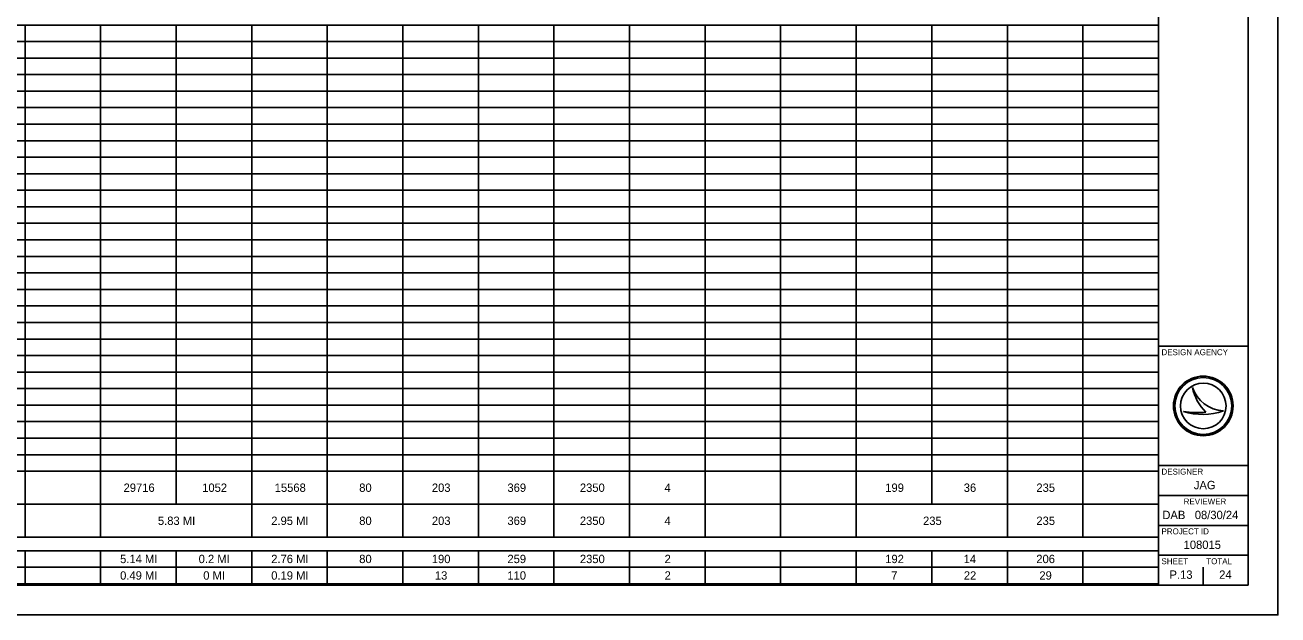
# Model space of a CAD drawing. Extents: x 0 to 34, y 0 to 22.
# Drawn here: x 13.03 to 34, y 0 to 9.88 of the extents above; entities that cross this region are included whole.
import ezdxf

# ---------------------------------------------------------------- set-up
doc = ezdxf.new("R2010")
doc.units = 0
for name, color, linetype in [('SH_Border', 7, 'Continuous'), ('SH_Cut_Line', 7, 'Continuous'), ('SH_Data', 7, 'Continuous'), ('SH_Text', 7, 'Continuous')]:
    doc.layers.add(name, color=color, linetype=linetype)

msp = doc.modelspace()

# ---------------------------------------------------------------- linework, layer by layer
at = {"layer": 'SH_Border'}
for p, q in [((32, 0.5), (32, 21.5)), ((32, 4.5), (33.5, 4.5)), ((32, 2.5), (33.5, 2.5)), ((32, 2), (33.5, 2)), ((32, 1.5), (33.5, 1.5)), ((32, 1), (33.5, 1))]:
    msp.add_line(p, q, dxfattribs=at)
msp.add_lwpolyline([(1.5, 21.5), (33.5, 21.5), (33.5, 0.5), (1.5, 0.5)], close=True, dxfattribs=at)
at = {"layer": 'SH_Cut_Line'}
msp.add_lwpolyline([(0, 0), (34, 0), (34, 22), (0, 22)], close=True, dxfattribs=at)
at = {"layer": 'SH_Data'}
for p, q in [((32.567, 3.81), (32.567, 3.81)), ((32.417, 3.41), (32.417, 3.41)), ((32.75, 3.5), (32.75, 3.5)), ((33.087, 3.419), (33.087, 3.419)), ((32.375, 0.675), (32.375, 0.675)), ((32.75, 0.5), (32.75, 0.8))]:
    msp.add_line(p, q, dxfattribs=at)
for radius in [0.5, 0.477, 0.477, 0.382]:
    msp.add_circle((32.75, 3.5), radius, dxfattribs=at)
for centre, radius, start, end in [((33.116, 3.998), 0.58, 198.9257, 198.9319), ((33.347, 3.97), 0.796, 191.6379, 191.6421), ((33.116, 3.998), 0.58, 198.9319, 267.1657), ((33.347, 3.97), 0.796, 191.6421, 226.0947), ((32.739, 4.37), 1.013, 251.4576, 290.0832), ((32.648, 4.654), 1.266, 259.4964, 259.4995), ((32.739, 4.37), 1.013, 251.4527, 251.4576), ((32.648, 4.654), 1.266, 259.4995, 276.6672)]:
    msp.add_arc(centre, radius, start, end, dxfattribs=at)
at = {"layer": 'SH_Text'}
for p, q in [((8.427, 9.878), (13.026, 9.878)), ((13.026, 9.878), (15.556, 9.878)), ((13.026, 9.878), (13.026, 9.325)), ((14.291, 9.878), (14.291, 9.325)), ((15.556, 9.878), (23.145, 9.878)), ((15.556, 9.878), (15.556, 9.325)), ((16.821, 9.878), (16.821, 9.325)), ((18.086, 9.878), (18.086, 9.325)), ((19.351, 9.878), (19.351, 9.325)), ((20.616, 9.878), (20.616, 9.325)), ((21.88, 9.878), (21.88, 9.325)), ((23.145, 9.878), (24.41, 9.878)), ((23.145, 9.878), (23.145, 9.325)), ((24.41, 9.878), (25.675, 9.878)), ((24.41, 9.878), (24.41, 9.325)), ((25.675, 9.878), (26.94, 9.878)), ((25.675, 9.878), (25.675, 9.325)), ((26.94, 9.878), (28.205, 9.878)), ((26.94, 9.878), (26.94, 9.325)), ((28.205, 9.878), (29.47, 9.878)), ((28.205, 9.878), (28.205, 9.325)), ((29.47, 9.878), (30.735, 9.878)), ((29.47, 9.878), (29.47, 9.325)), ((30.735, 9.878), (32, 9.878)), ((30.735, 9.878), (30.735, 9.325)), ((32, 9.878), (32, 9.325)), ((8.427, 9.602), (13.026, 9.602)), ((13.026, 9.602), (15.556, 9.602)), ((15.556, 9.602), (23.145, 9.602)), ((23.145, 9.602), (24.41, 9.602)), ((24.41, 9.602), (25.675, 9.602)), ((25.675, 9.602), (26.94, 9.602)), ((26.94, 9.602), (28.205, 9.602)), ((28.205, 9.602), (29.47, 9.602)), ((29.47, 9.602), (30.735, 9.602)), ((30.735, 9.602), (32, 9.602)), ((8.427, 9.325), (13.026, 9.325)), ((13.026, 9.325), (15.556, 9.325)), ((13.026, 9.325), (13.026, 8.495)), ((14.291, 9.325), (14.291, 8.495)), ((15.556, 9.325), (23.145, 9.325)), ((15.556, 9.325), (15.556, 8.495)), ((16.821, 9.325), (16.821, 8.495)), ((18.086, 9.325), (18.086, 8.495)), ((19.351, 9.325), (19.351, 8.495)), ((20.616, 9.325), (20.616, 8.495)), ((21.88, 9.325), (21.88, 8.495)), ((23.145, 9.325), (24.41, 9.325)), ((23.145, 9.325), (23.145, 8.495)), ((24.41, 9.325), (25.675, 9.325)), ((24.41, 9.325), (24.41, 8.495)), ((25.675, 9.325), (26.94, 9.325)), ((25.675, 9.325), (25.675, 8.495)), ((26.94, 9.325), (28.205, 9.325)), ((26.94, 9.325), (26.94, 8.495)), ((28.205, 9.325), (29.47, 9.325)), ((28.205, 9.325), (28.205, 8.495)), ((29.47, 9.325), (30.735, 9.325)), ((29.47, 9.325), (29.47, 8.495)), ((30.735, 9.325), (32, 9.325)), ((30.735, 9.325), (30.735, 8.495)), ((32, 9.325), (32, 8.495)), ((8.427, 9.048), (13.026, 9.048)), ((13.026, 9.048), (15.556, 9.048)), ((15.556, 9.048), (23.145, 9.048)), ((23.145, 9.048), (24.41, 9.048)), ((24.41, 9.048), (25.675, 9.048)), ((25.675, 9.048), (26.94, 9.048)), ((26.94, 9.048), (28.205, 9.048)), ((28.205, 9.048), (29.47, 9.048)), ((29.47, 9.048), (30.735, 9.048)), ((30.735, 9.048), (32, 9.048)), ((8.427, 8.772), (13.026, 8.772)), ((13.026, 8.772), (15.556, 8.772)), ((15.556, 8.772), (23.145, 8.772)), ((23.145, 8.772), (24.41, 8.772)), ((24.41, 8.772), (25.675, 8.772)), ((25.675, 8.772), (26.94, 8.772)), ((26.94, 8.772), (28.205, 8.772)), ((28.205, 8.772), (29.47, 8.772)), ((29.47, 8.772), (30.735, 8.772)), ((30.735, 8.772), (32, 8.772)), ((8.427, 8.495), (13.026, 8.495)), ((13.026, 8.495), (15.556, 8.495)), ((13.026, 8.495), (13.026, 7.941)), ((14.291, 8.495), (14.291, 7.941)), ((15.556, 8.495), (23.145, 8.495)), ((15.556, 8.495), (15.556, 7.941)), ((16.821, 8.495), (16.821, 7.941)), ((18.086, 8.495), (18.086, 7.941)), ((19.351, 8.495), (19.351, 7.941)), ((20.616, 8.495), (20.616, 7.941)), ((21.88, 8.495), (21.88, 7.941)), ((23.145, 8.495), (24.41, 8.495)), ((23.145, 8.495), (23.145, 7.941)), ((24.41, 8.495), (25.675, 8.495)), ((24.41, 8.495), (24.41, 7.941)), ((25.675, 8.495), (26.94, 8.495)), ((25.675, 8.495), (25.675, 7.941)), ((26.94, 8.495), (28.205, 8.495)), ((26.94, 8.495), (26.94, 7.941)), ((28.205, 8.495), (29.47, 8.495)), ((28.205, 8.495), (28.205, 7.941)), ((29.47, 8.495), (30.735, 8.495)), ((29.47, 8.495), (29.47, 7.941)), ((30.735, 8.495), (32, 8.495)), ((30.735, 8.495), (30.735, 7.941)), ((32, 8.495), (32, 7.941)), ((8.427, 8.218), (13.026, 8.218)), ((13.026, 8.218), (15.556, 8.218)), ((15.556, 8.218), (23.145, 8.218)), ((23.145, 8.218), (24.41, 8.218)), ((24.41, 8.218), (25.675, 8.218)), ((25.675, 8.218), (26.94, 8.218)), ((26.94, 8.218), (28.205, 8.218)), ((28.205, 8.218), (29.47, 8.218)), ((29.47, 8.218), (30.735, 8.218)), ((30.735, 8.218), (32, 8.218)), ((8.427, 7.941), (13.026, 7.941)), ((13.026, 7.941), (15.556, 7.941)), ((13.026, 7.941), (13.026, 7.111)), ((14.291, 7.941), (14.291, 7.111)), ((15.556, 7.941), (23.145, 7.941)), ((15.556, 7.941), (15.556, 7.111)), ((16.821, 7.941), (16.821, 7.111)), ((18.086, 7.941), (18.086, 7.111)), ((19.351, 7.941), (19.351, 7.111)), ((20.616, 7.941), (20.616, 7.111)), ((21.88, 7.941), (21.88, 7.111)), ((23.145, 7.941), (24.41, 7.941)), ((23.145, 7.941), (23.145, 7.111)), ((24.41, 7.941), (25.675, 7.941)), ((24.41, 7.941), (24.41, 7.111)), ((25.675, 7.941), (26.94, 7.941)), ((25.675, 7.941), (25.675, 7.111)), ((26.94, 7.941), (28.205, 7.941)), ((26.94, 7.941), (26.94, 7.111)), ((28.205, 7.941), (29.47, 7.941)), ((28.205, 7.941), (28.205, 7.111)), ((29.47, 7.941), (30.735, 7.941)), ((29.47, 7.941), (29.47, 7.111)), ((30.735, 7.941), (32, 7.941)), ((30.735, 7.941), (30.735, 7.111)), ((32, 7.941), (32, 7.111)), ((8.427, 7.665), (13.026, 7.665)), ((13.026, 7.665), (15.556, 7.665)), ((15.556, 7.665), (23.145, 7.665)), ((23.145, 7.665), (24.41, 7.665)), ((24.41, 7.665), (25.675, 7.665)), ((25.675, 7.665), (26.94, 7.665)), ((26.94, 7.665), (28.205, 7.665)), ((28.205, 7.665), (29.47, 7.665)), ((29.47, 7.665), (30.735, 7.665)), ((30.735, 7.665), (32, 7.665)), ((8.427, 7.388), (13.026, 7.388)), ((13.026, 7.388), (15.556, 7.388)), ((15.556, 7.388), (23.145, 7.388)), ((23.145, 7.388), (24.41, 7.388)), ((24.41, 7.388), (25.675, 7.388)), ((25.675, 7.388), (26.94, 7.388)), ((26.94, 7.388), (28.205, 7.388)), ((28.205, 7.388), (29.47, 7.388)), ((29.47, 7.388), (30.735, 7.388)), ((30.735, 7.388), (32, 7.388)), ((8.427, 7.111), (13.026, 7.111)), ((13.026, 7.111), (15.556, 7.111)), ((13.026, 7.111), (13.026, 6.558)), ((14.291, 7.111), (14.291, 6.558)), ((15.556, 7.111), (23.145, 7.111)), ((15.556, 7.111), (15.556, 6.558)), ((16.821, 7.111), (16.821, 6.558)), ((18.086, 7.111), (18.086, 6.558)), ((19.351, 7.111), (19.351, 6.558)), ((20.616, 7.111), (20.616, 6.558)), ((21.88, 7.111), (21.88, 6.558)), ((23.145, 7.111), (24.41, 7.111)), ((23.145, 7.111), (23.145, 6.558)), ((24.41, 7.111), (25.675, 7.111)), ((24.41, 7.111), (24.41, 6.558)), ((25.675, 7.111), (26.94, 7.111)), ((25.675, 7.111), (25.675, 6.558)), ((26.94, 7.111), (28.205, 7.111)), ((26.94, 7.111), (26.94, 6.558)), ((28.205, 7.111), (29.47, 7.111)), ((28.205, 7.111), (28.205, 6.558)), ((29.47, 7.111), (30.735, 7.111)), ((29.47, 7.111), (29.47, 6.558)), ((30.735, 7.111), (32, 7.111)), ((30.735, 7.111), (30.735, 6.558)), ((32, 7.111), (32, 6.558)), ((8.427, 6.835), (13.026, 6.835)), ((13.026, 6.835), (15.556, 6.835)), ((15.556, 6.835), (23.145, 6.835)), ((23.145, 6.835), (24.41, 6.835)), ((24.41, 6.835), (25.675, 6.835)), ((25.675, 6.835), (26.94, 6.835)), ((26.94, 6.835), (28.205, 6.835)), ((28.205, 6.835), (29.47, 6.835)), ((29.47, 6.835), (30.735, 6.835)), ((30.735, 6.835), (32, 6.835)), ((8.427, 6.558), (13.026, 6.558)), ((13.026, 6.558), (15.556, 6.558)), ((13.026, 6.558), (13.026, 1.3)), ((14.291, 6.558), (14.291, 1.3)), ((15.556, 6.558), (23.145, 6.558)), ((15.556, 6.558), (15.556, 1.854)), ((16.821, 6.558), (16.821, 1.3)), ((18.086, 6.558), (18.086, 1.3)), ((19.351, 6.558), (19.351, 1.3)), ((20.616, 6.558), (20.616, 1.3)), ((21.88, 6.558), (21.88, 1.3)), ((23.145, 6.558), (24.41, 6.558)), ((23.145, 6.558), (23.145, 1.3)), ((24.41, 6.558), (25.675, 6.558)), ((24.41, 6.558), (24.41, 1.3)), ((25.675, 6.558), (26.94, 6.558)), ((25.675, 6.558), (25.675, 1.3)), ((26.94, 6.558), (28.205, 6.558)), ((26.94, 6.558), (26.94, 1.3)), ((28.205, 6.558), (29.47, 6.558)), ((28.205, 6.558), (28.205, 1.854)), ((29.47, 6.558), (30.735, 6.558)), ((29.47, 6.558), (29.47, 1.3)), ((30.735, 6.558), (32, 6.558)), ((30.735, 6.558), (30.735, 1.3)), ((32, 6.558), (32, 0.523)), ((8.427, 6.281), (13.026, 6.281)), ((13.026, 6.281), (15.556, 6.281)), ((15.556, 6.281), (23.145, 6.281)), ((23.145, 6.281), (24.41, 6.281)), ((24.41, 6.281), (25.675, 6.281)), ((25.675, 6.281), (26.94, 6.281)), ((26.94, 6.281), (28.205, 6.281)), ((28.205, 6.281), (29.47, 6.281)), ((29.47, 6.281), (30.735, 6.281)), ((30.735, 6.281), (32, 6.281)), ((8.427, 6.004), (13.026, 6.004)), ((13.026, 6.004), (15.556, 6.004)), ((15.556, 6.004), (23.145, 6.004)), ((23.145, 6.004), (24.41, 6.004)), ((24.41, 6.004), (25.675, 6.004)), ((25.675, 6.004), (26.94, 6.004)), ((26.94, 6.004), (28.205, 6.004)), ((28.205, 6.004), (29.47, 6.004)), ((29.47, 6.004), (30.735, 6.004)), ((30.735, 6.004), (32, 6.004)), ((8.427, 5.728), (13.026, 5.728)), ((13.026, 5.728), (15.556, 5.728)), ((15.556, 5.728), (23.145, 5.728)), ((23.145, 5.728), (24.41, 5.728)), ((24.41, 5.728), (25.675, 5.728)), ((25.675, 5.728), (26.94, 5.728)), ((26.94, 5.728), (28.205, 5.728)), ((28.205, 5.728), (29.47, 5.728)), ((29.47, 5.728), (30.735, 5.728)), ((30.735, 5.728), (32, 5.728)), ((8.427, 5.451), (13.026, 5.451)), ((13.026, 5.451), (15.556, 5.451)), ((15.556, 5.451), (23.145, 5.451)), ((23.145, 5.451), (24.41, 5.451)), ((24.41, 5.451), (25.675, 5.451)), ((25.675, 5.451), (26.94, 5.451)), ((26.94, 5.451), (28.205, 5.451)), ((28.205, 5.451), (29.47, 5.451)), ((29.47, 5.451), (30.735, 5.451)), ((30.735, 5.451), (32, 5.451)), ((8.427, 5.174), (13.026, 5.174)), ((13.026, 5.174), (15.556, 5.174)), ((15.556, 5.174), (23.145, 5.174)), ((23.145, 5.174), (24.41, 5.174)), ((24.41, 5.174), (25.675, 5.174)), ((25.675, 5.174), (26.94, 5.174)), ((26.94, 5.174), (28.205, 5.174)), ((28.205, 5.174), (29.47, 5.174)), ((29.47, 5.174), (30.735, 5.174)), ((30.735, 5.174), (32, 5.174)), ((8.427, 4.898), (13.026, 4.898)), ((13.026, 4.898), (15.556, 4.898)), ((15.556, 4.898), (23.145, 4.898)), ((23.145, 4.898), (24.41, 4.898)), ((24.41, 4.898), (25.675, 4.898)), ((25.675, 4.898), (26.94, 4.898)), ((26.94, 4.898), (28.205, 4.898)), ((28.205, 4.898), (29.47, 4.898)), ((29.47, 4.898), (30.735, 4.898)), ((30.735, 4.898), (32, 4.898)), ((8.427, 4.621), (13.026, 4.621)), ((13.026, 4.621), (15.556, 4.621)), ((15.556, 4.621), (23.145, 4.621)), ((23.145, 4.621), (24.41, 4.621)), ((24.41, 4.621), (25.675, 4.621)), ((25.675, 4.621), (26.94, 4.621)), ((26.94, 4.621), (28.205, 4.621)), ((28.205, 4.621), (29.47, 4.621)), ((29.47, 4.621), (30.735, 4.621)), ((30.735, 4.621), (32, 4.621)), ((8.427, 4.344), (13.026, 4.344)), ((13.026, 4.344), (15.556, 4.344)), ((15.556, 4.344), (23.145, 4.344)), ((23.145, 4.344), (24.41, 4.344)), ((24.41, 4.344), (25.675, 4.344)), ((25.675, 4.344), (26.94, 4.344)), ((26.94, 4.344), (28.205, 4.344)), ((28.205, 4.344), (29.47, 4.344)), ((29.47, 4.344), (30.735, 4.344)), ((30.735, 4.344), (32, 4.344)), ((8.427, 4.068), (13.026, 4.068)), ((13.026, 4.068), (15.556, 4.068)), ((15.556, 4.068), (23.145, 4.068)), ((23.145, 4.068), (24.41, 4.068)), ((24.41, 4.068), (25.675, 4.068)), ((25.675, 4.068), (26.94, 4.068)), ((26.94, 4.068), (28.205, 4.068)), ((28.205, 4.068), (29.47, 4.068)), ((29.47, 4.068), (30.735, 4.068)), ((30.735, 4.068), (32, 4.068)), ((8.427, 3.791), (13.026, 3.791)), ((13.026, 3.791), (15.556, 3.791)), ((15.556, 3.791), (23.145, 3.791)), ((23.145, 3.791), (24.41, 3.791)), ((24.41, 3.791), (25.675, 3.791)), ((25.675, 3.791), (26.94, 3.791)), ((26.94, 3.791), (28.205, 3.791)), ((28.205, 3.791), (29.47, 3.791)), ((29.47, 3.791), (30.735, 3.791)), ((30.735, 3.791), (32, 3.791)), ((8.427, 3.514), (13.026, 3.514)), ((13.026, 3.514), (15.556, 3.514)), ((15.556, 3.514), (23.145, 3.514)), ((23.145, 3.514), (24.41, 3.514)), ((24.41, 3.514), (25.675, 3.514)), ((25.675, 3.514), (26.94, 3.514)), ((26.94, 3.514), (28.205, 3.514)), ((28.205, 3.514), (29.47, 3.514)), ((29.47, 3.514), (30.735, 3.514)), ((30.735, 3.514), (32, 3.514)), ((8.427, 3.237), (13.026, 3.237)), ((13.026, 3.237), (15.556, 3.237)), ((15.556, 3.237), (23.145, 3.237)), ((23.145, 3.237), (24.41, 3.237)), ((24.41, 3.237), (25.675, 3.237)), ((25.675, 3.237), (26.94, 3.237)), ((26.94, 3.237), (28.205, 3.237)), ((28.205, 3.237), (29.47, 3.237)), ((29.47, 3.237), (30.735, 3.237)), ((30.735, 3.237), (32, 3.237)), ((8.427, 2.961), (13.026, 2.961)), ((13.026, 2.961), (15.556, 2.961)), ((15.556, 2.961), (23.145, 2.961)), ((23.145, 2.961), (24.41, 2.961)), ((24.41, 2.961), (25.675, 2.961)), ((25.675, 2.961), (26.94, 2.961)), ((26.94, 2.961), (28.205, 2.961)), ((28.205, 2.961), (29.47, 2.961)), ((29.47, 2.961), (30.735, 2.961)), ((30.735, 2.961), (32, 2.961)), ((8.427, 2.684), (13.026, 2.684)), ((13.026, 2.684), (15.556, 2.684)), ((15.556, 2.684), (23.145, 2.684)), ((23.145, 2.684), (24.41, 2.684)), ((24.41, 2.684), (25.675, 2.684)), ((25.675, 2.684), (26.94, 2.684)), ((26.94, 2.684), (28.205, 2.684)), ((28.205, 2.684), (29.47, 2.684)), ((29.47, 2.684), (30.735, 2.684)), ((30.735, 2.684), (32, 2.684)), ((8.427, 2.407), (13.026, 2.407)), ((13.026, 2.407), (15.556, 2.407)), ((15.556, 2.407), (23.145, 2.407)), ((23.145, 2.407), (24.41, 2.407)), ((24.41, 2.407), (25.675, 2.407)), ((25.675, 2.407), (26.94, 2.407)), ((26.94, 2.407), (28.205, 2.407)), ((28.205, 2.407), (29.47, 2.407)), ((29.47, 2.407), (30.735, 2.407)), ((30.735, 2.407), (32, 2.407)), ((8.427, 1.854), (13.026, 1.854)), ((13.026, 1.854), (15.556, 1.854)), ((15.556, 1.854), (23.145, 1.854)), ((23.145, 1.854), (24.41, 1.854)), ((24.41, 1.854), (25.675, 1.854)), ((25.675, 1.854), (26.94, 1.854)), ((26.94, 1.854), (28.205, 1.854)), ((28.205, 1.854), (29.47, 1.854)), ((29.47, 1.854), (30.735, 1.854)), ((30.735, 1.854), (32, 1.854)), ((8.427, 1.3), (13.026, 1.3)), ((13.026, 1.3), (15.556, 1.3)), ((15.556, 1.3), (23.145, 1.3)), ((23.145, 1.3), (24.41, 1.3)), ((24.41, 1.3), (25.675, 1.3)), ((25.675, 1.3), (26.94, 1.3)), ((26.94, 1.3), (28.205, 1.3)), ((28.205, 1.3), (29.47, 1.3)), ((29.47, 1.3), (30.735, 1.3)), ((30.735, 1.3), (32, 1.3)), ((8.427, 1.076), (13.026, 1.076)), ((13.026, 1.076), (15.556, 1.076)), ((13.026, 1.076), (13.026, 0.523)), ((14.291, 1.076), (14.291, 0.523)), ((15.556, 1.076), (23.145, 1.076)), ((15.556, 1.076), (15.556, 0.523)), ((16.821, 1.076), (16.821, 0.523)), ((18.086, 1.076), (18.086, 0.523)), ((19.351, 1.076), (19.351, 0.523)), ((20.616, 1.076), (20.616, 0.523)), ((21.88, 1.076), (21.88, 0.523)), ((23.145, 1.076), (24.41, 1.076)), ((23.145, 1.076), (23.145, 0.523)), ((24.41, 1.076), (25.675, 1.076)), ((24.41, 1.076), (24.41, 0.523)), ((25.675, 1.076), (26.94, 1.076)), ((25.675, 1.076), (25.675, 0.523)), ((26.94, 1.076), (28.205, 1.076)), ((26.94, 1.076), (26.94, 0.523)), ((28.205, 1.076), (29.47, 1.076)), ((28.205, 1.076), (28.205, 0.523)), ((29.47, 1.076), (30.735, 1.076)), ((29.47, 1.076), (29.47, 0.523)), ((30.735, 1.076), (32, 1.076)), ((30.735, 1.076), (30.735, 0.523)), ((8.427, 0.8), (13.026, 0.8)), ((13.026, 0.8), (15.556, 0.8)), ((15.556, 0.8), (23.145, 0.8)), ((23.145, 0.8), (24.41, 0.8)), ((24.41, 0.8), (25.675, 0.8)), ((25.675, 0.8), (26.94, 0.8)), ((26.94, 0.8), (28.205, 0.8)), ((28.205, 0.8), (29.47, 0.8)), ((29.47, 0.8), (30.735, 0.8)), ((30.735, 0.8), (32, 0.8)), ((8.427, 0.523), (13.026, 0.523)), ((13.026, 0.523), (15.556, 0.523)), ((15.556, 0.523), (23.145, 0.523)), ((23.145, 0.523), (24.41, 0.523)), ((24.41, 0.523), (25.675, 0.523)), ((25.675, 0.523), (26.94, 0.523)), ((26.94, 0.523), (28.205, 0.523)), ((28.205, 0.523), (29.47, 0.523)), ((29.47, 0.523), (30.735, 0.523)), ((30.735, 0.523), (32, 0.523))]:
    msp.add_line(p, q, dxfattribs=at)

# ---------------------------------------------------------------- texts
at = {"layer": 'SH_Data'}
for s, height, p in [('DESIGN AGENCY', 0.1, (32.05, 4.35)), ('DESIGNER', 0.1, (32.05, 2.35)), ('JAG', 0.14, (32.592, 2.105)), ('REVIEWER', 0.1, (32.422, 1.85)), ('DAB', 0.14, (32.065, 1.605)), ('08/30/24', 0.14, (32.608, 1.605)), ('PROJECT ID', 0.1, (32.05, 1.35)), ('108015', 0.14, (32.421, 1.105)), ('SHEET', 0.1, (32.05, 0.85)), ('TOTAL', 0.1, (32.8, 0.85)), ('P.13', 0.14, (32.185, 0.605)), ('24', 0.14, (33.016, 0.605))]:
    msp.add_text(s, height=height, dxfattribs=at).set_placement(p)
at = {"layer": 'SH_Text'}
for s, p in [('29716', (14.675, 2.061)), ('1052', (15.991, 2.061)), ('15568', (17.205, 2.061)), ('80', (18.62, 2.061)), ('203', (19.836, 2.061)), ('369', (21.101, 2.061)), ('2350', (22.314, 2.061)), ('4', (23.73, 2.061)), ('199', (27.426, 2.061)), ('36', (28.74, 2.061)), ('235', (29.956, 2.061)), ('5.83 MI', (15.25, 1.507)), ('2.95 MI', (17.147, 1.507)), ('80', (18.62, 1.507)), ('203', (19.836, 1.507)), ('369', (21.101, 1.507)), ('2350', (22.314, 1.507)), ('4', (23.73, 1.507)), ('235', (28.059, 1.507)), ('235', (29.956, 1.507)), ('5.14 MI', (14.617, 0.868)), ('0.2 MI', (15.932, 0.868)), ('2.76 MI', (17.147, 0.868)), ('80', (18.62, 0.868)), ('190', (19.835, 0.868)), ('259', (21.101, 0.868)), ('2350', (22.314, 0.868)), ('2', (23.732, 0.868)), ('192', (27.426, 0.868)), ('14', (28.739, 0.868)), ('206', (29.955, 0.868)), ('0.49 MI', (14.617, 0.591)), ('0 MI', (16.009, 0.591)), ('0.19 MI', (17.147, 0.591)), ('13', (19.887, 0.591)), ('110', (21.1, 0.591)), ('2', (23.732, 0.591)), ('7', (27.526, 0.591)), ('22', (28.741, 0.591)), ('29', (30.006, 0.591))]:
    msp.add_text(s, height=0.14, dxfattribs=at).set_placement(p)

doc.saveas('drawing.dxf')
